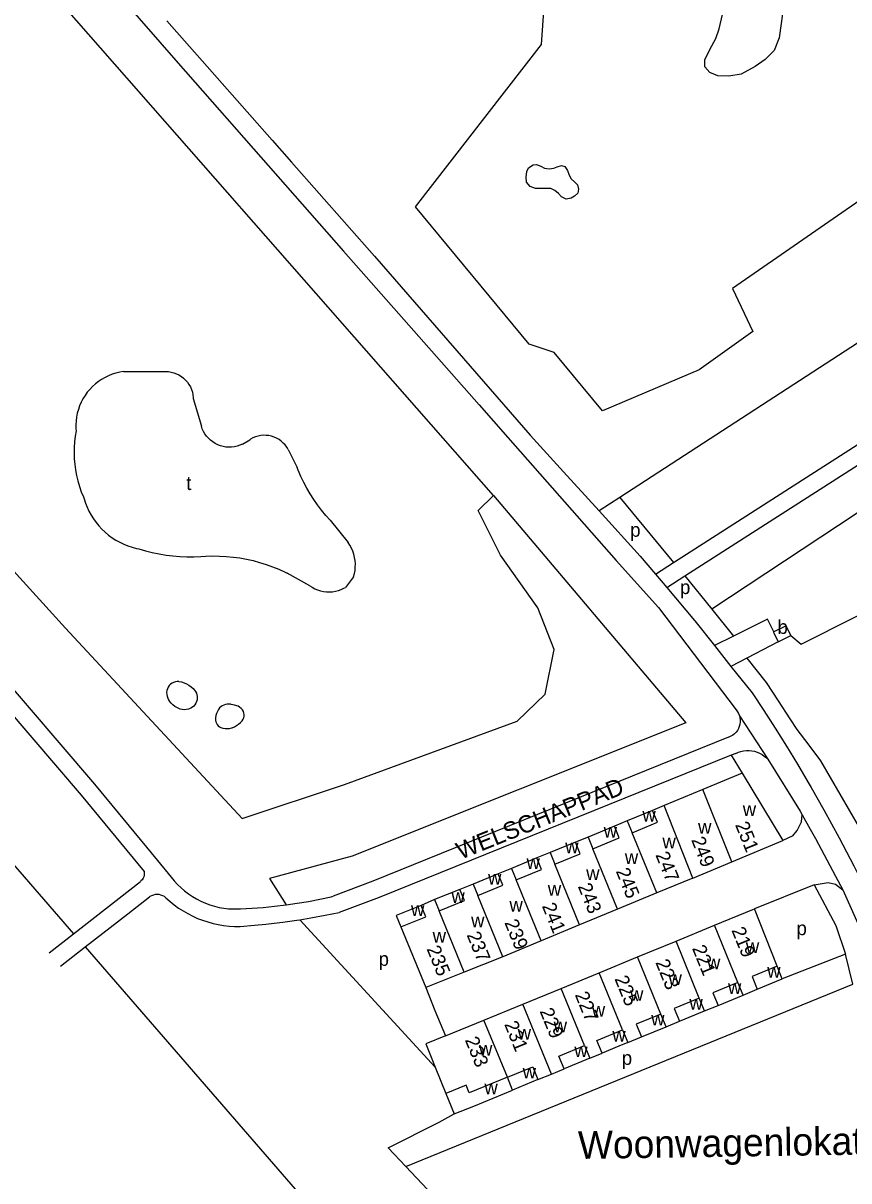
# Model space of a CAD drawing. Extents: x 156066 to 157805, y 383432 to 385631.
# Drawn here: x 157328.2 to 157566.3, y 383825.9 to 384159.6 of the extents above; entities that cross this region are included whole.
import ezdxf

# ---------------------------------------------------------------- set-up
doc = ezdxf.new("R2010")
doc.units = 0
for name, color, linetype in [('BLT_Basislijn', 7, 'Continuous'), ('BLT_Bebouwing', 7, 'Continuous'), ('BLT_Centroide', 7, 'Continuous'), ('BLT_Huisnummer', 7, 'Continuous'), ('BLT_Huisnummer_ tussenligend', 7, 'Continuous'), ('BLT_Straatnaam', 7, 'Continuous'), ('BLT_Terrein_beschrifting', 7, 'Continuous')]:
    doc.layers.add(name, color=color, linetype=linetype)

msp = doc.modelspace()

# ---------------------------------------------------------------- linework, layer by layer
at = {"layer": 'BLT_Basislijn'}
for p, q in [((157340.74, 384184.93), (157372.94, 384148.06)), ((157369.67, 384160.28), (157381.29, 384147.11)), ((157372.94, 384148.06), (157420.53, 384093.88)), ((157381.29, 384147.11), (157400.03, 384125.85)), ((157400.03, 384125.85), (157405.61, 384119.52)), ((157515.77, 384004.13), (157700.4, 384122.66)), ((157405.61, 384119.52), (157429.47, 384092.45)), ((157519.01, 384000.26), (157702.64, 384118.16)), ((157420.53, 384093.88), (157459.69, 384049.57)), ((157429.47, 384092.45), (157474.43, 384040.89)), ((157644.02, 384068.13), (157526.75, 383990.68)), ((157357.14, 384059.17), (157368.5, 384059.17)), ((157377.27, 384051.43), (157379.59, 384043.42)), ((157459.69, 384049.57), (157467.99, 384040.18)), ((157474.43, 384040.89), (157484.03, 384030.31)), ((157391.47, 384038.26), (157393.53, 384039.55)), ((157404.63, 384036.71), (157407.21, 384031.55)), ((157484.03, 384030.31), (157494.28, 384019.01)), ((157500.22, 384022.86), (157494.28, 384019.01)), ((157500.22, 384022.86), (157515.77, 384004.13)), ((157416.76, 384016.31), (157421.92, 384009.86)), ((157510.52, 384000.76), (157515.77, 384004.13)), ((157410.82, 383997.46), (157404.37, 384001.08)), ((157423.47, 384000.05), (157421.14, 383996.95)), ((157510.52, 384000.76), (157513.78, 383996.91)), ((157513.78, 383996.91), (157519.01, 384000.26)), ((157519.01, 384000.26), (157526.75, 383990.68)), ((157513.78, 383996.91), (157521.81, 383987.42)), ((157526.75, 383990.68), (157533, 383982.94)), ((157533, 383982.94), (157527.55, 383980.2)), ((157527.55, 383980.2), (157532.3, 383974.2)), ((157545.89, 383981.26), (157536.82, 383976.55)), ((157536.82, 383976.55), (157532.3, 383974.2)), ((157536.82, 383976.55), (157542.41, 383969.5)), ((157532.3, 383974.2), (157538.37, 383966.55)), ((157387.95, 383963.25), (157387.03, 383963.25)), ((157534.73, 383959.98), (157542.9, 383947.42)), ((157533.7, 383949.12), (157532.34, 383948.57)), ((157532.34, 383948.57), (157535.49, 383943.38)), ((157535.49, 383943.38), (157524.14, 383938.67)), ((157535.49, 383943.38), (157547.24, 383923.96)), ((157524.14, 383938.67), (157513.05, 383934.06)), ((157513.05, 383934.06), (157509.7, 383932.67)), ((157552.84, 383931.37), (157555.15, 383927.25)), ((157502.39, 383929.64), (157498.7, 383928.08)), ((157555.15, 383927.25), (157556.62, 383924.61)), ((157491.11, 383924.98), (157487.49, 383923.51)), ((157510.89, 383908.87), (157503.8, 383926.22)), ((157532.54, 383917.86), (157547.24, 383923.96)), ((157550.09, 383925.31), (157547.24, 383923.96)), ((157556.62, 383924.61), (157562.42, 383913.72)), ((157480.13, 383920.5), (157476.33, 383918.96)), ((157499.6, 383904.2), (157492.48, 383921.62)), ((157366.95, 383918.21), (157370.89, 383913.42)), ((157488.64, 383899.66), (157481.49, 383917.16)), ((157521.26, 383913.17), (157532.54, 383917.86)), ((157399.25, 383913.04), (157404, 383905.43)), ((157468.98, 383915.96), (157465.2, 383914.39)), ((157562.42, 383913.72), (157564.5, 383909.81)), ((157342.76, 383897.12), (157362.02, 383912.18)), ((157457.96, 383911.43), (157454.1, 383909.91)), ((157477.52, 383895.05), (157470.34, 383912.64)), ((157556.26, 383911.23), (157539.07, 383904.27)), ((157556.26, 383911.23), (157560.33, 383911.89)), ((157564.5, 383909.81), (157571.7, 383893.78)), ((157358.35, 383902.86), (157364.6, 383907.71)), ((157446.85, 383906.94), (157442.93, 383905.3)), ((157466.54, 383890.44), (157459.29, 383908.17)), ((157455.4, 383886.01), (157448.18, 383903.68)), ((157545.59, 383887.74), (157539.07, 383904.27)), ((157346.04, 383893.34), (157358.35, 383902.86)), ((157407.96, 383901.16), (157447.04, 383858.69)), ((157335.74, 383891.59), (157342.76, 383897.12)), ((157437.14, 383899.11), (157444.27, 383881.59)), ((157534.29, 383883.09), (157527.57, 383899.55)), ((157338.98, 383887.78), (157346.04, 383893.34)), ((157523.17, 383878.51), (157516.45, 383894.98)), ((157512.08, 383873.95), (157505.35, 383890.42)), ((157565.27, 383891.25), (157547.1, 383884.1)), ((157567.4, 383882.53), (157565.27, 383891.25)), ((157501.03, 383869.4), (157494.3, 383885.88)), ((157438.58, 383829.98), (157567.4, 383882.53)), ((157444.27, 383881.59), (157446.95, 383875.01)), ((157490.05, 383864.88), (157483.31, 383881.36)), ((157535.8, 383879.44), (157539.89, 383881.13)), ((157480.53, 383856.65), (157472.28, 383876.83)), ((157524.68, 383874.86), (157528.57, 383876.46)), ((157446.95, 383875.01), (157449.95, 383867.66)), ((157467.82, 383855.72), (157461.08, 383872.23)), ((157513.59, 383870.28), (157517.42, 383871.86)), ((157502.54, 383865.73), (157506.47, 383867.35)), ((157491.56, 383861.2), (157495.17, 383862.69)), ((157447.04, 383858.69), (157450.11, 383851.08)), ((157476.64, 383855.05), (157480.53, 383856.65)), ((157480.53, 383856.65), (157484.2, 383858.17)), ((157448.13, 383842.76), (157452.51, 383845.22)), ((157433.43, 383835.43), (157448.13, 383842.76)), ((157438.58, 383829.98), (157433.43, 383835.43)), ((157457.51, 383809.98), (157438.58, 383829.98))]:
    msp.add_line(p, q, dxfattribs=at)
for points in [[(157463.86, 384023.42), (157317.96, 384189.64), (157152.75, 384380.64), (157052.19, 384495.7)], [(157088.75, 384280.38), (157125.95, 384248.8), (157138.38, 384224.9), (157179.5, 384177.08), (157199.58, 384143.61), (157248.35, 384085.28), (157269.97, 384055.34), (157304.71, 384024.5), (157340.39, 383985.23), (157391.35, 383930.37), (157420.88, 383940.11), (157470.65, 383958.4), (157478.75, 383966.19), (157481.29, 383979.08), (157476.65, 383991.08), (157465.85, 384006.22), (157459.4, 384019.12), (157463.86, 384023.42)], [(157754.15, 384189.17), (157700, 384153.26), (157578.07, 384073.38), (157500.22, 384022.86)], [(157614.03, 384164.34), (157610.59, 384150.01), (157599.69, 384137), (157599.8, 384129.56), (157532.7, 384083.09), (157538.59, 384070.78), (157523.17, 384059.72), (157495.28, 384047.88), (157481.32, 384064.7), (157474.08, 384067.11), (157441.34, 384106.71), (157477.7, 384153.46), (157478.43, 384164.44)], [(157547.36, 384163.8), (157546.76, 384159.53), (157546.16, 384155.4), (157544.74, 384151.73), (157542.19, 384149.11), (157539.27, 384147.09), (157535.22, 384144.91), (157531.7, 384144.31), (157528.47, 384144.46), (157526.23, 384145.44), (157524.8, 384147.01), (157524.73, 384149.03), (157526.23, 384152.03), (157527.95, 384155.18), (157528.85, 384158.03), (157529.82, 384162.15)], [(157156.52, 384111.66), (157253.52, 384000), (157342.76, 383897.12)], [(157357.14, 384059.17), (157356.04, 384058.99), (157354.94, 384058.73), (157353.87, 384058.39), (157352.83, 384057.98), (157351.82, 384057.49), (157350.84, 384056.93), (157349.91, 384056.31), (157349.03, 384055.62), (157348.19, 384054.87), (157347.42, 384054.06), (157346.7, 384053.2), (157346.04, 384052.28), (157345.45, 384051.33), (157344.93, 384050.33), (157344.49, 384049.3), (157344.12, 384048.24), (157343.82, 384047.16), (157343.6, 384046.06), (157343.46, 384044.95), (157343.4, 384043.83), (157343.42, 384042.71), (157343.46, 384042.13)], [(157368.5, 384059.17), (157369.3, 384059.21), (157370.1, 384059.16), (157370.89, 384059.04), (157371.67, 384058.83), (157372.42, 384058.55), (157373.14, 384058.2), (157373.82, 384057.78), (157374.45, 384057.29), (157375.04, 384056.74), (157375.56, 384056.13), (157376.02, 384055.48), (157376.42, 384054.78), (157376.74, 384054.05), (157376.99, 384053.28), (157377.17, 384052.5), (157377.26, 384051.71), (157377.27, 384051.43)], [(157391.47, 384038.26), (157390.71, 384037.93), (157389.93, 384037.67), (157389.13, 384037.49), (157388.32, 384037.39), (157387.49, 384037.37), (157386.68, 384037.43), (157385.87, 384037.57), (157385.07, 384037.79), (157384.3, 384038.08), (157383.57, 384038.44), (157382.87, 384038.88), (157382.22, 384039.38), (157381.62, 384039.94), (157381.08, 384040.56), (157380.6, 384041.23), (157380.19, 384041.94), (157379.85, 384042.69), (157379.59, 384043.42)], [(157343.46, 384042.13), (157343.2, 384040.53), (157343.02, 384038.92), (157342.92, 384037.29), (157342.9, 384035.67), (157342.95, 384034.05), (157343.09, 384032.43), (157343.31, 384030.82), (157343.6, 384029.22), (157343.98, 384027.64), (157344.43, 384026.08), (157344.96, 384024.54), (157345.56, 384023.03), (157345.79, 384022.51)], [(157404.63, 384036.71), (157404.22, 384037.38), (157403.75, 384038.02), (157403.21, 384038.59), (157402.63, 384039.12), (157401.99, 384039.58), (157401.3, 384039.97), (157400.58, 384040.29), (157399.84, 384040.54), (157399.07, 384040.71), (157398.28, 384040.8), (157397.5, 384040.81), (157396.71, 384040.74), (157395.94, 384040.59), (157395.18, 384040.37), (157394.46, 384040.07), (157393.76, 384039.7), (157393.53, 384039.55)], [(157467.99, 384040.18), (157499.24, 384004.72), (157511.41, 383991.13), (157533.84, 383961.64)], [(157549.57, 383983.08), (157552.57, 383980.57), (157660.24, 384034.75)], [(157416.76, 384016.31), (157415.47, 384017.73), (157414.24, 384019.2), (157413.08, 384020.72), (157411.98, 384022.29), (157410.95, 384023.9), (157409.99, 384025.56), (157409.09, 384027.25), (157408.27, 384028.98), (157407.52, 384030.74), (157407.21, 384031.55)], [(157463.86, 384023.42), (157519.27, 383957.9), (157423.1, 383919.46), (157399.25, 383913.04)], [(157345.79, 384022.51), (157346.18, 384021.29), (157346.65, 384020.1), (157347.19, 384018.93), (157347.8, 384017.81), (157348.49, 384016.73), (157349.23, 384015.68), (157350.05, 384014.69), (157350.92, 384013.75), (157351.85, 384012.87), (157352.83, 384012.05), (157353.86, 384011.29), (157354.94, 384010.6), (157356.06, 384009.97), (157357.21, 384009.41), (157358.4, 384008.93), (157359.61, 384008.53), (157360.85, 384008.2), (157361.53, 384008.05)], [(157494.28, 384019.01), (157506.16, 384005.92), (157510.52, 384000.76)], [(157285.53, 384010.47), (157319.53, 383974.29), (157348.76, 383940.24), (157366.95, 383918.21)], [(157423.47, 384000.05), (157423.71, 384000.95), (157423.89, 384001.87), (157423.98, 384002.81), (157423.99, 384003.75), (157423.92, 384004.68), (157423.77, 384005.61), (157423.55, 384006.52), (157423.25, 384007.41), (157422.87, 384008.27), (157422.42, 384009.1), (157421.92, 384009.86)], [(157281.89, 384007.05), (157315.81, 383970.95), (157344.93, 383937.03), (157363.1, 383915.03)], [(157361.53, 384008.05), (157363.47, 384007.49), (157365.43, 384007.02), (157367.41, 384006.62), (157369.4, 384006.3), (157371.41, 384006.05), (157373.42, 384005.89), (157375.43, 384005.81), (157377.45, 384005.8), (157379.47, 384005.88), (157380.89, 384005.98)], [(157380.89, 384005.98), (157382.85, 384006.04), (157384.81, 384006.01), (157386.76, 384005.9), (157388.72, 384005.71), (157390.66, 384005.44), (157392.59, 384005.09), (157394.5, 384004.67), (157396.4, 384004.16), (157398.27, 384003.58), (157400.12, 384002.93), (157401.94, 384002.19), (157403.73, 384001.39), (157404.37, 384001.08)], [(157410.82, 383997.46), (157411.55, 383996.99), (157412.31, 383996.58), (157413.11, 383996.24), (157413.94, 383995.98), (157414.79, 383995.79), (157415.65, 383995.68), (157416.52, 383995.66), (157417.39, 383995.71), (157418.24, 383995.84), (157419.09, 383996.05), (157419.91, 383996.34), (157420.7, 383996.7), (157421.14, 383996.95)], [(157521.81, 383987.42), (157521.9, 383987.31), (157527.55, 383980.2)], [(157544.65, 383984.11), (157542.78, 383987.84), (157533, 383982.94)], [(157373.14, 383969.85), (157372.62, 383969.84), (157372.1, 383969.75), (157371.6, 383969.58), (157371.14, 383969.33), (157370.71, 383969.02), (157370.34, 383968.65), (157370.03, 383968.22), (157369.79, 383967.76), (157369.61, 383967.22)], [(157373.14, 383969.85), (157373.89, 383969.69), (157374.62, 383969.45), (157375.33, 383969.14), (157375.99, 383968.75), (157376.62, 383968.3), (157377.19, 383967.78), (157377.62, 383967.3)], [(157369.61, 383967.22), (157369.56, 383966.67), (157369.59, 383966.11), (157369.69, 383965.57), (157369.88, 383965.05), (157370.14, 383964.55), (157370.32, 383964.29)], [(157377.62, 383967.3), (157377.93, 383966.91), (157378.16, 383966.48), (157378.33, 383966.01), (157378.41, 383965.53), (157378.42, 383965.03), (157378.35, 383964.58)], [(157538.37, 383966.55), (157541.74, 383961.48), (157545.05, 383956.37), (157548.3, 383951.21), (157551.47, 383946.01), (157554.58, 383940.76), (157555.43, 383939.29)], [(157542.41, 383969.5), (157545.92, 383964.23), (157549.27, 383959.05), (157551.32, 383956.04), (157554.47, 383951.89), (157558.11, 383946.93), (157569.27, 383927.73)], [(157371.96, 383962.66), (157371.4, 383963.09), (157370.89, 383963.57), (157370.44, 383964.12), (157370.32, 383964.29)], [(157378.35, 383964.58), (157378.22, 383964.07), (157378.02, 383963.58), (157377.74, 383963.14), (157377.4, 383962.74), (157377, 383962.39), (157376.55, 383962.11), (157376.07, 383961.91), (157375.84, 383961.83)], [(157387.03, 383963.25), (157386.54, 383963.19), (157386.07, 383963.05), (157385.62, 383962.84), (157385.22, 383962.56), (157384.86, 383962.22), (157384.53, 383961.75)], [(157390.22, 383962.72), (157389.19, 383963.01), (157388.14, 383963.22), (157387.95, 383963.25)], [(157375.84, 383961.83), (157375.24, 383961.73), (157374.64, 383961.71), (157374.04, 383961.76), (157373.45, 383961.9), (157372.88, 383962.11), (157372.35, 383962.39), (157371.96, 383962.66)], [(157384.53, 383961.75), (157384.21, 383961.2), (157383.97, 383960.61), (157383.8, 383960), (157383.71, 383959.37), (157383.71, 383958.65)], [(157391.76, 383961.14), (157391.43, 383961.63), (157391.04, 383962.08), (157390.6, 383962.46), (157390.22, 383962.72)], [(157391.63, 383958.93), (157391.8, 383959.36), (157391.9, 383959.82), (157391.93, 383960.28), (157391.87, 383960.75), (157391.76, 383961.14)], [(157534.73, 383959.98), (157534.89, 383959.37), (157534.96, 383958.74), (157534.95, 383958.11), (157534.87, 383957.49), (157534.7, 383956.88), (157534.46, 383956.29), (157534.15, 383955.74), (157533.77, 383955.24), (157533.33, 383954.79), (157532.84, 383954.39), (157532.3, 383954.07), (157531.72, 383953.81), (157531.54, 383953.75)], [(157533.84, 383961.64), (157534.21, 383961.12), (157534.51, 383960.57), (157534.73, 383959.98)], [(157534.74, 383959.98), (157534.74, 383959.95)], [(157383.71, 383958.65), (157383.78, 383958.22), (157383.93, 383957.8), (157384.15, 383957.42), (157384.44, 383957.08), (157384.78, 383956.8), (157385.17, 383956.59)], [(157385.17, 383956.59), (157385.79, 383956.4), (157386.42, 383956.29), (157387.06, 383956.26), (157387.7, 383956.3), (157388.33, 383956.43), (157388.48, 383956.48)], [(157388.48, 383956.48), (157389.14, 383956.75), (157389.76, 383957.1), (157390.34, 383957.51), (157390.86, 383957.99), (157391.33, 383958.53), (157391.63, 383958.93)], [(157531.54, 383953.75), (157429.03, 383912.23), (157417.61, 383907.94)], [(157533.7, 383949.12), (157534.42, 383949.43), (157535.17, 383949.67), (157535.94, 383949.84), (157536.73, 383949.92), (157537.52, 383949.93), (157538.3, 383949.85), (157539.08, 383949.7), (157539.83, 383949.46), (157540.56, 383949.16), (157541.25, 383948.78), (157541.9, 383948.33), (157542.51, 383947.82), (157542.9, 383947.42)], [(157532.34, 383948.57), (157430.85, 383907.57), (157419.37, 383903.26)], [(157542.9, 383947.42), (157552.21, 383932.49), (157552.84, 383931.37)], [(157532.54, 383917.86), (157524.14, 383938.67)], [(157555.43, 383939.29), (157559.1, 383932.82), (157563.48, 383924.8), (157567.68, 383916.68), (157570.58, 383910.88), (157577.8, 383895.07), (157585.02, 383879.25), (157594.32, 383856.8), (157603.63, 383834.36), (157608.4, 383823.97)], [(157521.26, 383913.17), (157513.05, 383934.06)], [(157550.09, 383925.31), (157551.41, 383926.89), (157552.67, 383929.36), (157552.84, 383931.37)], [(157363.1, 383915.03), (157363.13, 383914.53), (157363.09, 383914.04), (157362.97, 383913.56), (157362.77, 383913.1), (157362.5, 383912.68), (157362.17, 383912.32), (157362.02, 383912.18)], [(157370.89, 383913.42), (157371.77, 383912.36), (157372.71, 383911.34), (157373.72, 383910.38), (157374.77, 383909.48), (157375.88, 383908.64), (157377.03, 383907.86), (157378.23, 383907.16), (157379.46, 383906.52), (157380.74, 383905.96), (157382.04, 383905.46), (157383.36, 383905.05), (157384.71, 383904.71), (157386.07, 383904.45), (157387.45, 383904.27), (157387.56, 383904.26)], [(157521.26, 383913.17), (157510.89, 383908.87)], [(157556.26, 383911.23), (157562.51, 383899.51), (157565.27, 383891.25)], [(157560.33, 383911.89), (157562.43, 383911.39), (157564.5, 383909.81)], [(157369.39, 383907.47), (157368.95, 383907.8), (157368.46, 383908.07), (157367.95, 383908.27), (157367.4, 383908.39), (157366.85, 383908.43), (157366.3, 383908.39), (157365.76, 383908.27), (157365.24, 383908.08), (157364.76, 383907.81), (157364.6, 383907.71)], [(157369.39, 383907.47), (157370.55, 383906.43), (157371.77, 383905.45), (157373.03, 383904.53), (157374.34, 383903.68), (157375.7, 383902.9), (157377.09, 383902.19), (157378.51, 383901.55), (157379.96, 383900.99), (157381.45, 383900.5), (157382.95, 383900.08), (157384.48, 383899.75), (157386.02, 383899.49), (157387.57, 383899.31), (157389.13, 383899.21), (157390.69, 383899.2), (157390.8, 383899.2)], [(157404, 383905.43), (157407.26, 383905.9), (157410.51, 383906.45), (157413.75, 383907.08), (157416.97, 383907.79), (157417.61, 383907.94)], [(157510.89, 383908.87), (157499.6, 383904.2)], [(157387.56, 383904.26), (157390.86, 383904.33), (157394.15, 383904.49), (157397.44, 383904.72), (157400.72, 383905.03), (157404, 383905.43)], [(157407.96, 383901.16), (157411.2, 383901.69), (157415.24, 383902.42), (157419.37, 383903.26)], [(157499.6, 383904.2), (157488.64, 383899.66)], [(157527.57, 383899.55), (157538.62, 383904.09), (157539.07, 383904.27)], [(157390.8, 383899.2), (157394.89, 383899.54), (157398.15, 383899.87)], [(157398.15, 383899.87), (157398.99, 383899.96), (157403.07, 383900.45), (157407.14, 383901.03), (157407.96, 383901.16)], [(157488.64, 383899.66), (157477.52, 383895.05)], [(157516.45, 383894.98), (157527.57, 383899.55)], [(157346.04, 383893.34), (157407.92, 383821.99), (157470.36, 383750), (157500, 383715.82)], [(157477.52, 383895.05), (157466.54, 383890.44)], [(157505.35, 383890.42), (157516.45, 383894.98)], [(157466.54, 383890.44), (157455.4, 383886.01)], [(157494.3, 383885.88), (157505.35, 383890.42)], [(157455.4, 383886.01), (157444.27, 383881.59)], [(157483.31, 383881.36), (157494.3, 383885.88)], [(157472.28, 383876.83), (157483.31, 383881.36)], [(157461.08, 383872.23), (157472.28, 383876.83)], [(157449.95, 383867.66), (157461.08, 383872.23)], [(157449.95, 383867.66), (157444.36, 383865.36), (157447.04, 383858.69)]]:
    msp.add_lwpolyline(points, dxfattribs=at)
msp.add_lwpolyline([(157475.22, 384118.79), (157476.23, 384118.9), (157477.47, 384118.42), (157478.52, 384117.85), (157479.87, 384117.59), (157481.18, 384117.78), (157482.16, 384118.19), (157483.39, 384118.6), (157484.4, 384118.34), (157485.19, 384117.18), (157485.64, 384115.83), (157486.24, 384114.78), (157487.21, 384113.88), (157488.08, 384112.98), (157488.34, 384111.78), (157488.11, 384110.62), (157487.21, 384109.72), (157486.2, 384109.16), (157484.74, 384108.86), (157483.43, 384109.57), (157482.53, 384110.55), (157481.48, 384111.41), (157480.36, 384111.93), (157478.45, 384111.93), (157475.93, 384111.93), (157474.36, 384112.53), (157473.35, 384113.81), (157473.2, 384115.19), (157473.39, 384116.84), (157473.95, 384117.93)], close=True, dxfattribs=at)
at = {"layer": 'BLT_Bebouwing'}
for p, q in [((157509.7, 383932.67), (157502.39, 383929.64)), ((157498.7, 383928.08), (157491.11, 383924.98)), ((157500.07, 383924.73), (157498.7, 383928.08)), ((157487.49, 383923.51), (157480.13, 383920.5)), ((157476.33, 383918.96), (157468.98, 383915.96)), ((157465.2, 383914.39), (157457.96, 383911.43)), ((157454.1, 383909.91), (157446.85, 383906.94)), ((157442.93, 383905.3), (157435.8, 383902.39)), ((157435.8, 383902.39), (157437.14, 383899.11)), ((157547.1, 383884.1), (157545.59, 383887.74)), ((157539.89, 383881.13), (157547.1, 383884.1)), ((157528.57, 383876.46), (157535.8, 383879.44)), ((157517.42, 383871.86), (157524.68, 383874.86)), ((157506.47, 383867.35), (157513.59, 383870.28)), ((157491.56, 383861.2), (157484.2, 383858.17)), ((157476.64, 383855.05), (157469.34, 383852.04)), ((157450.11, 383851.08), (157452.51, 383845.22)), ((157458.2, 383847.44), (157469.34, 383852.04)), ((157452.51, 383845.22), (157458.2, 383847.44))]:
    msp.add_line(p, q, dxfattribs=at)
for points in [[(157544.65, 383984.11), (157544.52, 383984.04), (157545.89, 383981.26)], [(157549.57, 383983.08), (157548.18, 383985.84), (157544.65, 383984.11)], [(157545.89, 383981.26), (157549.57, 383983.08)], [(157503.8, 383926.22), (157511.11, 383929.25), (157509.7, 383932.67)], [(157502.39, 383929.64), (157503.8, 383926.22)], [(157481.49, 383917.16), (157488.86, 383920.16), (157487.49, 383923.51)], [(157491.11, 383924.98), (157492.48, 383921.62)], [(157492.48, 383921.62), (157500.07, 383924.73)], [(157480.13, 383920.5), (157481.49, 383917.16)], [(157470.34, 383912.64), (157477.68, 383915.64), (157476.33, 383918.96)], [(157459.29, 383908.17), (157466.53, 383911.13), (157465.2, 383914.39)], [(157468.98, 383915.96), (157470.34, 383912.64)], [(157448.18, 383903.68), (157455.43, 383906.65), (157454.1, 383909.91)], [(157457.96, 383911.43), (157459.29, 383908.17)], [(157446.85, 383906.94), (157448.18, 383903.68)], [(157437.14, 383899.11), (157444.27, 383902.03), (157442.93, 383905.3)], [(157545.59, 383887.74), (157538.38, 383884.77), (157539.89, 383881.13)], [(157534.29, 383883.09), (157527.06, 383880.11), (157528.57, 383876.46)], [(157535.8, 383879.44), (157534.29, 383883.09)], [(157523.17, 383878.51), (157515.91, 383875.52), (157517.42, 383871.86)], [(157524.68, 383874.86), (157523.17, 383878.51)], [(157512.08, 383873.95), (157504.96, 383871.01), (157506.47, 383867.35)], [(157513.59, 383870.28), (157512.08, 383873.95)], [(157495.17, 383862.69), (157493.63, 383866.35), (157501.03, 383869.4)], [(157501.03, 383869.4), (157502.54, 383865.73)], [(157484.2, 383858.17), (157482.68, 383861.84), (157490.05, 383864.88)], [(157490.05, 383864.88), (157491.56, 383861.2)], [(157502.54, 383865.73), (157500, 383864.68), (157495.17, 383862.69)], [(157467.82, 383855.72), (157475.12, 383858.73), (157476.64, 383855.05)], [(157467.82, 383855.72), (157456.85, 383851.25), (157455.94, 383853.49), (157450.11, 383851.08)], [(157469.34, 383852.04), (157467.82, 383855.72)]]:
    msp.add_lwpolyline(points, dxfattribs=at)

# ---------------------------------------------------------------- texts
at = {"layer": 'BLT_Centroide'}
for s, p in [('t', (157375.24, 384025.03)), ('p', (157503.24, 384011.56)), ('p', (157517.6, 383995.04)), ('b', (157545.71, 383983.56)), ('w', (157535.69, 383931.09)), ('w', (157506.75, 383929.44)), ('w', (157495.59, 383924.84)), ('w', (157522.8, 383925.95)), ('w', (157484.49, 383920.34)), ('w', (157512.53, 383921.7)), ('w', (157501.69, 383917.2)), ('w', (157473.34, 383915.81)), ('w', (157462.25, 383911.28)), ('w', (157490.55, 383912.59)), ('w', (157479.48, 383908.06)), ('w', (157451.68, 383906)), ('w', (157468.41, 383903.47)), ('w', (157440.03, 383902.22)), ('w', (157457.36, 383898.98)), ('p', (157551.19, 383896.7)), ('w', (157446.27, 383894.53)), ('w', (157536.58, 383891.52)), ('p', (157430.71, 383887.85)), ('w', (157525.38, 383886.89)), ('w', (157542.73, 383884.44)), ('w', (157514.27, 383882.31)), ('w', (157503.19, 383877.77)), ('w', (157531.43, 383879.78)), ('w', (157520.3, 383875.19)), ('w', (157492.17, 383873.22)), ('w', (157509.27, 383870.66)), ('w', (157470.8, 383866.58)), ('w', (157481.17, 383868.69)), ('w', (157498.08, 383866.03)), ('w', (157459.64, 383861.98)), ('w', (157487.12, 383861.53)), ('p', (157500.82, 383859.31)), ('w', (157472.23, 383855.38)), ('w', (157461.2, 383850.84))]:
    msp.add_text(s, height=4, dxfattribs=at).set_placement(p)
at = {"layer": 'BLT_Huisnummer'}
for s, rotation, p in [('251', 291.9896, (157533.43, 383928.53)), ('247', 292.1611, (157510.45, 383919.85)), ('243', 292.1611, (157488.08, 383910.78)), ('239', 292.1611, (157466.91, 383900.35)), ('219', 292.1607, (157532.37, 383898.15)), ('235', 292.1611, (157444.47, 383892.78)), ('223', 292.1607, (157510.45, 383888.85)), ('229', 292.1607, (157477.07, 383874.81)), ('233', 292.1611, (157455.51, 383866.51))]:
    msp.add_text(s, height=4, rotation=rotation, dxfattribs=at).set_placement(p)
at = {"layer": 'BLT_Huisnummer_ tussenligend'}
for s, rotation, p in [('249', 291.4374, (157520.78, 383924.21)), ('245', 292.1611, (157499.03, 383915.17)), ('241', 292.1611, (157477.73, 383905.12)), ('237', 292.1611, (157456.02, 383896.8)), ('221', 292.1607, (157521.01, 383892.93)), ('225', 292.1607, (157498.65, 383884.14)), ('227', 292.1607, (157487.22, 383879.53)), ('231', 292.1607, (157466.86, 383871.04))]:
    msp.add_text(s, height=4, rotation=rotation, dxfattribs=at).set_placement(p)
at = {"layer": 'BLT_Straatnaam'}
msp.add_text('WELSCHAPPAD', height=5, rotation=21.9929, dxfattribs=at).set_placement((157454.36, 383918.43))
at = {"layer": 'BLT_Terrein_beschrifting'}
msp.add_text('Woonwagenlokatie', height=7.9999, rotation=0.8717, dxfattribs=at).set_placement((157488.24, 383832.18))

doc.saveas('drawing.dxf')
